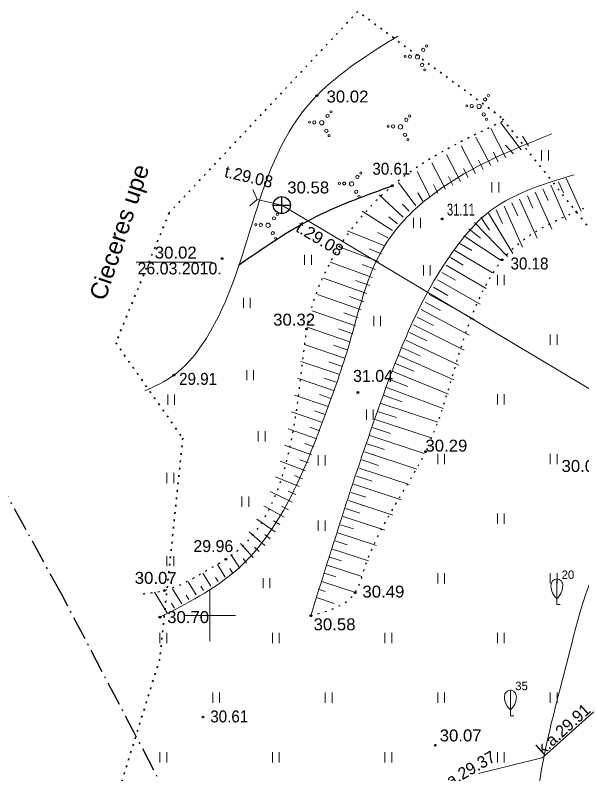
# Model space of a CAD drawing. Extents: x 380758 to 381729, y 283236 to 283533.
# Drawn here: x 381588.57 to 381621.82, y 283440.71 to 283485.22 of the extents above; entities that cross this region are included whole.
import ezdxf
from ezdxf.enums import TextEntityAlignment as Align

# ---------------------------------------------------------------- set-up
doc = ezdxf.new("R2010")
doc.units = 0
doc.header["$LTSCALE"] = 0.28
doc.linetypes.add('DOT_DASHED', pattern=[7.7, 5, -1.2, 0.3, -1.2])
doc.linetypes.add('DOTTED', pattern=[1.5, 0.3, -1.2])
for name, color, linetype, lineweight in [('1', 7, 'Continuous', 13), ('21', 7, 'Continuous', 25), ('23', 7, 'Continuous', 13), ('25', 7, 'DOTTED', 35), ('29', 7, 'DOT_DASHED', 25), ('30', 7, 'Continuous', 13), ('31', 7, 'Continuous', 13), ('35', 7, 'Continuous', 13), ('36', 7, 'Continuous', 13), ('38', 7, 'Continuous', 25), ('47', 7, 'Continuous', 13), ('58', 7, 'Continuous', 25), ('62', 7, 'Continuous', 13), ('7', 7, 'Continuous', 13)]:
    doc.layers.add(name, color=color, linetype=linetype, lineweight=lineweight)

msp = doc.modelspace()

# ---------------------------------------------------------------- linework, layer by layer
at = {"layer": '1'}
for p, q in [((381620.355, 283452.143), (381620.355, 283450.995)), ((381620.355, 283450.995), (381620.355, 283450.643)), ((381620.355, 283450.643), (381620.555, 283450.643)), ((381617.633, 283445.62), (381617.633, 283444.472)), ((381617.633, 283444.472), (381617.633, 283444.12)), ((381617.633, 283444.12), (381617.833, 283444.12))]:
    msp.add_line(p, q, dxfattribs=at)
for centre, major_axis, start_param, end_param in [((381620.355, 283451.743), (0, 0.4), 0, 1.5707963), ((381620.355, 283451.743), (0, -0.4), 1.5707963, 3.1415927), ((381620.355, 283451.743), (0, -0.4), 1.5707963, 3.1415927), ((381620.8303, 283451.7664), (0, -0.9434), 4.7372004, 5.6697113), ((381619.8797, 283451.7664), (0, -0.9434), 0.613474, 1.5459849), ((381617.633, 283445.22), (0, 0.4), 0, 1.5707963), ((381617.633, 283445.22), (0, -0.4), 1.5707963, 3.1415927), ((381617.633, 283445.22), (0, -0.4), 1.5707963, 3.1415927), ((381618.1083, 283445.2434), (0, -0.9434), 4.7372004, 5.6697113), ((381617.1577, 283445.2434), (0, -0.9434), 0.613474, 1.5459849)]:
    msp.add_ellipse(centre, major_axis=major_axis, ratio=0.875, start_param=start_param, end_param=end_param, dxfattribs=at)
at = {"layer": '21'}
msp.add_spline([(381601.67, 283470.552), (381606.239, 283473.41), (381610.7, 283475.206)], degree=3, dxfattribs=at)
at = {"layer": '23'}
for p, q in [((381619.459, 283476.691), (381619.459, 283477.291)), ((381619.859, 283476.691), (381619.859, 283477.291)), ((381616.543, 283474.825), (381616.543, 283475.425)), ((381616.943, 283474.825), (381616.943, 283475.425)), ((381611.954, 283472.72), (381611.954, 283473.32)), ((381612.354, 283472.72), (381612.354, 283473.32)), ((381605.555, 283470.565), (381605.555, 283471.165)), ((381605.955, 283470.565), (381605.955, 283471.165)), ((381612.528, 283469.946), (381612.528, 283470.546)), ((381612.928, 283469.946), (381612.928, 283470.546)), ((381616.867, 283469.382), (381616.867, 283469.982)), ((381617.267, 283469.382), (381617.267, 283469.982)), ((381601.97, 283468.03), (381601.97, 283468.63)), ((381602.37, 283468.03), (381602.37, 283468.63)), ((381609.612, 283466.98), (381609.612, 283467.58)), ((381610.012, 283466.98), (381610.012, 283467.58)), ((381619.967, 283465.882), (381619.967, 283466.482)), ((381620.367, 283465.882), (381620.367, 283466.482)), ((381602.165, 283463.797), (381602.165, 283464.397)), ((381602.565, 283463.797), (381602.565, 283464.397)), ((381597.529, 283462.362), (381597.529, 283462.962)), ((381597.929, 283462.362), (381597.929, 283462.962)), ((381616.867, 283462.382), (381616.867, 283462.982)), ((381617.267, 283462.382), (381617.267, 283462.982)), ((381609.182, 283461.479), (381609.182, 283462.079)), ((381609.582, 283461.479), (381609.582, 283462.079)), ((381602.834, 283460.209), (381602.834, 283460.809)), ((381603.234, 283460.209), (381603.234, 283460.809)), ((381606.361, 283458.801), (381606.361, 283459.401)), ((381606.761, 283458.801), (381606.761, 283459.401)), ((381613.367, 283458.882), (381613.367, 283459.482)), ((381613.767, 283458.882), (381613.767, 283459.482)), ((381619.967, 283458.882), (381619.967, 283459.482)), ((381620.367, 283458.882), (381620.367, 283459.482)), ((381597.481, 283457.77), (381597.481, 283458.37)), ((381597.881, 283457.77), (381597.881, 283458.37)), ((381601.878, 283456.382), (381601.878, 283456.982)), ((381602.278, 283456.382), (381602.278, 283456.982)), ((381616.867, 283455.382), (381616.867, 283455.982)), ((381617.267, 283455.382), (381617.267, 283455.982)), ((381606.361, 283454.974), (381606.361, 283455.574)), ((381606.761, 283454.974), (381606.761, 283455.574)), ((381597.481, 283452.89), (381597.481, 283453.49)), ((381597.881, 283452.89), (381597.881, 283453.49)), ((381613.367, 283451.882), (381613.367, 283452.482)), ((381613.767, 283451.882), (381613.767, 283452.482)), ((381619.967, 283451.882), (381619.967, 283452.482)), ((381620.367, 283451.882), (381620.367, 283452.482)), ((381603.121, 283451.599), (381603.121, 283452.199)), ((381603.521, 283451.599), (381603.521, 283452.199)), ((381597.067, 283448.382), (381597.067, 283448.982)), ((381597.467, 283448.382), (381597.467, 283448.982)), ((381603.667, 283448.382), (381603.667, 283448.982)), ((381604.067, 283448.382), (381604.067, 283448.982)), ((381610.267, 283448.382), (381610.267, 283448.982)), ((381610.667, 283448.382), (381610.667, 283448.982)), ((381616.867, 283448.382), (381616.867, 283448.982)), ((381617.267, 283448.382), (381617.267, 283448.982)), ((381600.167, 283444.882), (381600.167, 283445.482)), ((381600.567, 283444.882), (381600.567, 283445.482)), ((381606.767, 283444.882), (381606.767, 283445.482)), ((381607.167, 283444.882), (381607.167, 283445.482)), ((381613.367, 283444.882), (381613.367, 283445.482)), ((381613.767, 283444.882), (381613.767, 283445.482)), ((381619.967, 283444.882), (381619.967, 283445.482)), ((381620.367, 283444.882), (381620.367, 283445.482)), ((381597.067, 283441.382), (381597.067, 283441.982)), ((381597.467, 283441.382), (381597.467, 283441.982)), ((381603.667, 283441.382), (381603.667, 283441.982)), ((381604.067, 283441.382), (381604.067, 283441.982)), ((381610.267, 283441.382), (381610.267, 283441.982)), ((381610.667, 283441.382), (381610.667, 283441.982)), ((381616.867, 283441.382), (381616.867, 283441.982)), ((381617.267, 283441.382), (381617.267, 283441.982))]:
    msp.add_line(p, q, dxfattribs=at)
at = {"layer": '25'}
msp.add_lwpolyline([(381656.478, 283407.485), (381656.785, 283411.384), (381679.837, 283414.706), (381691.271, 283419.627), (381696.042, 283430.549), (381696.103, 283435.47), (381692.415, 283454.909), (381687.812, 283460.539), (381693.775, 283478.441), (381690.524, 283484.916), (381662.554, 283506.139), (381648.108, 283480.856), (381643.628, 283460.038), (381633.547, 283458.315), (381623.737, 283470.857), (381617.098, 283479.223), (381608.676, 283485.436), (381597.611, 283473.625), (381594.476, 283465.997), (381598.41, 283460.399), (381597.059, 283447.446), (381591.712, 283430.203), (381578.864, 283403.443)], dxfattribs=at)
at = {"layer": '29'}
msp.add_lwpolyline([(381646.05, 283378.842), (381606.798, 283421.7), (381591.309, 283451.227), (381583.305, 283465.736)], dxfattribs=at)
at = {"layer": '30'}
for points in [[(381600, 283451.5), (381600, 283450), (381600, 283448.5)], [(381598.5, 283450), (381600, 283450), (381601.5, 283450)]]:
    msp.add_lwpolyline(points, dxfattribs=at)
at = {"layer": '31'}
for p, q in [((381618.253, 283477.315), (381617.056, 283478.916)), ((381617.366, 283476.853), (381616.475, 283478.566)), ((381616.479, 283476.392), (381615.611, 283478.061)), ((381618.697, 283477.545), (381618.349, 283478.129)), ((381615.591, 283475.931), (381614.746, 283477.556)), ((381617.809, 283477.084), (381617.351, 283477.593)), ((381614.704, 283475.469), (381613.881, 283477.052)), ((381616.922, 283476.623), (381616.632, 283477.18)), ((381613.817, 283475.008), (381613.017, 283476.547)), ((381616.035, 283476.161), (381615.752, 283476.704)), ((381612.93, 283474.547), (381612.152, 283476.042)), ((381615.148, 283475.7), (381614.873, 283476.229)), ((381614.26, 283475.239), (381613.993, 283475.753)), ((381620.907, 283475.649), (381621.773, 283473.721)), ((381612.076, 283474.028), (381611.058, 283475.403)), ((381613.373, 283474.777), (381613.113, 283475.277)), ((381619.994, 283475.239), (381620.91, 283473.2)), ((381620.451, 283475.444), (381620.744, 283474.79)), ((381611.33, 283473.364), (381609.939, 283474.676)), ((381612.491, 283474.306), (381612.2, 283474.787)), ((381619.082, 283474.829), (381620.052, 283472.67)), ((381619.538, 283475.034), (381619.85, 283474.34)), ((381618.17, 283474.419), (381619.194, 283472.14)), ((381618.626, 283474.624), (381618.956, 283473.891)), ((381611.688, 283473.713), (381611.309, 283474.139)), ((381616.802, 283473.805), (381617.167, 283472.991)), ((381617.258, 283474.01), (381618.336, 283471.61)), ((381617.714, 283474.215), (381618.061, 283473.441)), ((381610.713, 283472.579), (381608.938, 283473.728)), ((381611.004, 283472.986), (381610.503, 283473.38)), ((381615.902, 283473.37), (381616.412, 283472.597)), ((381616.346, 283473.6), (381617.764, 283471.245)), ((381615.515, 283473.055), (381617.459, 283471.069)), ((381610.256, 283471.692), (381608.052, 283472.557)), ((381610.462, 283472.147), (381609.836, 283472.47)), ((381615.184, 283472.681), (381615.872, 283472.142)), ((381614.893, 283472.274), (381617.081, 283470.831)), ((381609.896, 283470.758), (381607.522, 283471.657)), ((381614.628, 283471.851), (381615.36, 283471.409)), ((381610.075, 283471.226), (381609.338, 283471.509)), ((381614.37, 283471.422), (381616.574, 283470.105)), ((381609.547, 283469.821), (381607.065, 283470.732)), ((381614.115, 283470.993), (381614.867, 283470.547)), ((381609.721, 283470.29), (381608.928, 283470.586)), ((381613.861, 283470.562), (381616.207, 283469.187)), ((381609.207, 283468.881), (381606.668, 283469.791)), ((381613.609, 283470.13), (381614.411, 283469.666)), ((381609.376, 283469.352), (381608.547, 283469.652)), ((381613.36, 283469.696), (381615.861, 283468.269)), ((381613.114, 283469.261), (381613.968, 283468.781)), ((381608.872, 283467.939), (381606.317, 283468.838)), ((381609.039, 283468.41), (381608.192, 283468.711)), ((381612.87, 283468.824), (381615.532, 283467.356)), ((381612.631, 283468.385), (381613.538, 283467.895)), ((381608.542, 283466.995), (381606.003, 283467.879)), ((381608.707, 283467.467), (381607.854, 283467.765)), ((381612.395, 283467.945), (381615.216, 283466.452)), ((381612.163, 283467.501), (381613.123, 283467.006)), ((381608.214, 283466.05), (381605.716, 283466.917)), ((381608.378, 283466.523), (381607.544, 283466.812)), ((381611.936, 283467.056), (381614.909, 283465.561)), ((381611.714, 283466.608), (381612.721, 283466.116)), ((381607.889, 283465.104), (381605.554, 283465.896)), ((381608.051, 283465.578), (381607.251, 283465.852)), ((381611.497, 283466.157), (381614.606, 283464.685)), ((381611.286, 283465.704), (381612.335, 283465.224)), ((381607.57, 283464.157), (381605.34, 283464.904)), ((381607.73, 283464.631), (381606.975, 283464.884)), ((381611.081, 283465.248), (381614.304, 283463.825)), ((381610.882, 283464.789), (381611.965, 283464.33)), ((381610.691, 283464.328), (381614, 283462.982)), ((381607.253, 283463.208), (381605.148, 283463.916)), ((381607.412, 283463.682), (381606.695, 283463.922)), ((381610.506, 283463.863), (381611.619, 283463.431)), ((381610.329, 283463.395), (381613.69, 283462.153)), ((381606.931, 283462.261), (381604.968, 283462.934)), ((381607.093, 283462.735), (381606.421, 283462.962)), ((381610.159, 283462.925), (381611.276, 283462.534)), ((381609.998, 283462.452), (381613.369, 283461.338)), ((381606.604, 283461.316), (381604.784, 283461.944)), ((381606.768, 283461.789), (381606.145, 283462.006)), ((381609.842, 283461.977), (381610.943, 283461.616)), ((381609.687, 283461.501), (381612.988, 283460.42)), ((381606.28, 283460.37), (381604.587, 283460.95)), ((381606.442, 283460.843), (381605.862, 283461.042)), ((381609.531, 283461.026), (381610.6, 283460.676)), ((381609.375, 283460.551), (381612.581, 283459.501)), ((381605.952, 283459.426), (381604.372, 283459.986)), ((381606.118, 283459.898), (381605.578, 283460.085)), ((381609.22, 283460.076), (381610.247, 283459.739)), ((381609.064, 283459.601), (381612.146, 283458.591)), ((381605.783, 283458.955), (381605.279, 283459.139)), ((381608.908, 283459.126), (381609.887, 283458.805)), ((381605.608, 283458.487), (381604.131, 283459.049)), ((381608.753, 283458.65), (381611.69, 283457.688)), ((381605.427, 283458.021), (381604.956, 283458.209)), ((381605.237, 283457.558), (381603.854, 283458.142)), ((381608.597, 283458.175), (381609.523, 283457.872)), ((381608.441, 283457.7), (381611.219, 283456.79)), ((381604.827, 283456.646), (381603.537, 283457.268)), ((381605.038, 283457.1), (381604.598, 283457.297)), ((381608.286, 283457.225), (381609.155, 283456.94)), ((381604.364, 283455.76), (381603.173, 283456.434)), ((381608.13, 283456.75), (381610.739, 283455.895)), ((381604.603, 283456.199), (381604.195, 283456.412)), ((381607.974, 283456.275), (381608.787, 283456.009)), ((381603.837, 283454.911), (381602.761, 283455.646)), ((381604.11, 283455.33), (381603.737, 283455.561)), ((381607.819, 283455.8), (381610.256, 283455.001)), ((381607.663, 283455.324), (381608.419, 283455.077)), ((381603.231, 283454.115), (381602.301, 283454.908)), ((381603.545, 283454.505), (381603.215, 283454.756)), ((381607.507, 283454.849), (381609.776, 283454.106)), ((381602.537, 283453.396), (381601.79, 283454.219)), ((381607.352, 283454.374), (381608.055, 283454.144)), ((381602.896, 283453.745), (381602.621, 283454.01)), ((381607.196, 283453.899), (381609.304, 283453.208)), ((381601.752, 283452.779), (381601.22, 283453.569)), ((381602.156, 283453.073), (381601.947, 283453.338)), ((381607.041, 283453.424), (381607.717, 283453.202)), ((381600.903, 283452.251), (381600.453, 283452.984)), ((381606.885, 283452.949), (381608.914, 283452.284)), ((381600.05, 283451.728), (381599.582, 283452.492)), ((381601.329, 283452.512), (381601.174, 283452.764)), ((381606.729, 283452.474), (381607.385, 283452.259)), ((381599.198, 283451.205), (381598.724, 283451.978)), ((381600.477, 283451.99), (381600.327, 283452.234)), ((381606.574, 283451.998), (381608.54, 283451.354)), ((381598.346, 283450.682), (381597.804, 283451.565)), ((381599.624, 283451.467), (381599.468, 283451.721)), ((381606.418, 283451.523), (381606.763, 283451.41)), ((381597.493, 283450.159), (381596.755, 283451.364)), ((381598.772, 283450.944), (381598.614, 283451.202)), ((381597.919, 283450.421), (381597.739, 283450.715)), ((381606.262, 283451.048), (381607.297, 283450.709))]:
    msp.add_line(p, q, dxfattribs=at)
at = {"layer": '31', "linetype": 'DOTTED', "lineweight": 25}
for points in [[(381617.172, 283478.984), (381610.7, 283475.206), (381605.674, 283466.808), (381605.545, 283465.902), (381600.936, 283453.297), (381600.299, 283452.919), (381597.326, 283451.458), (381596.069, 283451.25)], [(381605.914, 283449.985), (381608.523, 283451.336), (381609.043, 283452.675), (381612.645, 283459.615), (381613.232, 283460.977), (381616.519, 283469.948), (381617.156, 283470.87), (381622.255, 283474.019)]]:
    msp.add_spline(points, degree=3, dxfattribs=at)
at = {"layer": '31'}
for points in [[(381597.067, 283449.898), (381601.519, 283452.629), (381606.725, 283461.664), (381608.189, 283465.978), (381610.26, 283471.702), (381612.781, 283474.47), (381620.061, 283478.255)], [(381621.363, 283475.853), (381616.198, 283473.534), (381614.612, 283471.824), (381609.975, 283462.382), (381605.914, 283449.985)]]:
    msp.add_spline(points, degree=3, dxfattribs=at)
at = {"layer": '35'}
msp.add_spline([(381625.172, 283455.605), (381624.353, 283454.972), (381621.078, 283447.765), (381619.239, 283434.927), (381620.318, 283430.21), (381621.325, 283424.09)], degree=3, dxfattribs=at)
at = {"layer": '36'}
msp.add_line((381595.666, 283470.722), (381600.13, 283470.722), dxfattribs=at)
msp.add_spline([(381596.174, 283463.171), (381597.882, 283464.101), (381599.527, 283465.872), (381605.739, 283479.912), (381606.274, 283480.496), (381611.022, 283483.984)], degree=3, dxfattribs=at)
at = {"layer": '38'}
for p, q in [((381604.22, 283473.576), (381604.22, 283474.576)), ((381603.72, 283474.076), (381604.72, 283474.076))]:
    msp.add_line(p, q, dxfattribs=at)
msp.add_circle((381604.22, 283474.076), 0.5, dxfattribs=at)
at = {"layer": '47'}
msp.add_line((381602.779, 283474.411), (381602.334, 283474.03), dxfattribs=at)
msp.add_lwpolyline([(381681.769, 283444.455), (381677.901, 283460.031), (381638.443, 283453.634), (381604.22, 283474.076), (381602.779, 283474.411), (381602.525, 283474.983)], dxfattribs=at)
at = {"layer": '58'}
for centre, radius in [((381606.274, 283480.4961), 0.0534), ((381610.7, 283475.2061), 0.0534), ((381613.625, 283473.2661), 0.0534), ((381600.721, 283470.941), 0.05), ((381617.156, 283470.8701), 0.0534), ((381605.674, 283466.8081), 0.0534), ((381597.882, 283464.1011), 0.0534), ((381608.686, 283463.0811), 0.0534), ((381612.645, 283459.6151), 0.0534), ((381600.936, 283453.2971), 0.0534), ((381597.326, 283451.4581), 0.0534), ((381608.523, 283451.3361), 0.0534), ((381597.067, 283449.8981), 0.0534), ((381605.914, 283449.9851), 0.0534), ((381599.596, 283444.0411), 0.0534), ((381613.227, 283442.3871), 0.0534)]:
    msp.add_circle(centre, radius, dxfattribs=at)
at = {"layer": '62'}
for centre, radius in [((381612.52, 283483.1792), 0.096), ((381612.7165, 283483.4109), 0.064), ((381611.4541, 283482.8057), 0.064), ((381611.7385, 283482.7923), 0.096), ((381612.1725, 283482.7715), 0.128), ((381612.4489, 283482.3046), 0.096), ((381612.6064, 283482.0153), 0.064), ((381616.3389, 283480.5029), 0.064), ((381616.1424, 283480.2712), 0.096), ((381607.1037, 283479.5469), 0.064), ((381615.0765, 283479.8978), 0.064), ((381615.361, 283479.8843), 0.096), ((381615.7949, 283479.8635), 0.128), ((381606.9072, 283479.3152), 0.096), ((381611.5248, 283479.0762), 0.096), ((381611.7213, 283479.3078), 0.064), ((381616.0714, 283479.3967), 0.096), ((381616.2288, 283479.1074), 0.064), ((381605.8413, 283478.9417), 0.064), ((381606.1258, 283478.9283), 0.096), ((381606.5597, 283478.9075), 0.128), ((381610.4589, 283478.7027), 0.064), ((381610.7434, 283478.6893), 0.096), ((381611.1773, 283478.6685), 0.128), ((381606.8362, 283478.4406), 0.096), ((381611.4538, 283478.2016), 0.096), ((381606.9936, 283478.1513), 0.064), ((381611.6112, 283477.9123), 0.064), ((381608.8552, 283475.9617), 0.064), ((381608.6587, 283475.73), 0.096), ((381607.5928, 283475.3566), 0.064), ((381607.8773, 283475.3431), 0.096), ((381608.3112, 283475.3223), 0.128), ((381608.5877, 283474.8555), 0.096), ((381608.7451, 283474.5662), 0.064), ((381603.7625, 283473.3001), 0.096), ((381603.959, 283473.5318), 0.064), ((381602.6966, 283472.9266), 0.064), ((381602.981, 283472.9132), 0.096), ((381603.415, 283472.8924), 0.128), ((381603.6914, 283472.4255), 0.096), ((381603.8489, 283472.1362), 0.064)]:
    msp.add_circle(centre, radius, dxfattribs=at)
at = {"layer": '7'}
msp.add_line((381619.475, 283441.654), (381615.838, 283440.742), dxfattribs=at)
msp.add_lwpolyline([(381626.233, 283447.115), (381625.18, 283446.376), (381622.412, 283444.253), (381619.602, 283441.722)], dxfattribs=at)
for centre, start, end in [((381619.4017, 283441.9448), 284.07579, 312.01482), ((381615.911, 283440.4511), 104.07579, 119.75509)]:
    msp.add_arc(centre, 0.3, start, end, dxfattribs=at)

# ---------------------------------------------------------------- texts
at = {"layer": '1'}
for s, p in [('20', (381620.635, 283452.143)), ('35', (381617.913, 283445.62))]:
    msp.add_text(s, height=0.5, dxfattribs=at).set_placement(p)
at = {"layer": '36', "width": 1.05}
msp.add_text('Cieceres upe', height=1, rotation=71.581, dxfattribs=at).set_placement((381593.846, 283468.409))
msp.add_text('30.02', height=0.7, dxfattribs=at).set_placement((381596.767, 283470.94))
at = {"layer": '36'}
msp.add_text('26.03.2010.', height=0.7, dxfattribs=at).set_placement((381595.751, 283470.01))
at = {"layer": '38', "width": 1.05}
msp.add_text('30.58', height=0.7, dxfattribs=at).set_placement((381604.537, 283474.76))
at = {"layer": '47'}
msp.add_text('t.29.08', height=0.7, rotation=346.905, dxfattribs=at).set_placement((381602.2047, 283475.4029), align=Align.CENTER)
at = {"layer": '47', "width": 1.05}
msp.add_text('t.29.08', height=0.7, rotation=329.149, dxfattribs=at).set_placement((381606.27, 283471.8035), align=Align.CENTER)
at = {"layer": '58'}
for s, width, p in [('30.02', 1.05, (381606.842, 283480.097)), ('30.61', 0.95, (381609.534, 283475.86)), ('31.11', 0.7, (381613.909, 283473.465)), ('30.18', 0.95, (381617.639, 283470.3)), ('30.32', 1.05, (381603.712, 283467.007)), ('29.91', 0.95, (381598.194, 283463.531)), ('30.29', 1.05, (381612.645, 283459.615)), ('30.05', 1.05, (381620.63, 283458.422)), ('30.07', 1.05, (381595.591, 283451.856)), ('30.49', 1.05, (381608.949, 283451.051)), ('30.70', 1.05, (381597.493, 283449.556)), ('30.58', 1.05, (381606.084, 283449.131)), ('30.61', 0.95, (381600.022, 283443.728)), ('30.07', 1.05, (381613.482, 283442.614))]:
    msp.add_text(s, height=0.7, dxfattribs=dict(at, width=width)).set_placement(p)
for s, p in [('31.04', (381608.401, 283463.706)), ('29.96', (381599.03, 283453.723))]:
    msp.add_text(s, height=0.7, dxfattribs=at).set_placement(p)
at = {"layer": '7'}
for s, rotation, p in [('k.a.29.91', 42.015, (381619.535, 283441.789)), ('k.a.29.37', 29.755, (381613.493, 283439.584))]:
    msp.add_text(s, height=0.7, rotation=rotation, dxfattribs=at).set_placement(p)

doc.saveas('drawing.dxf')
